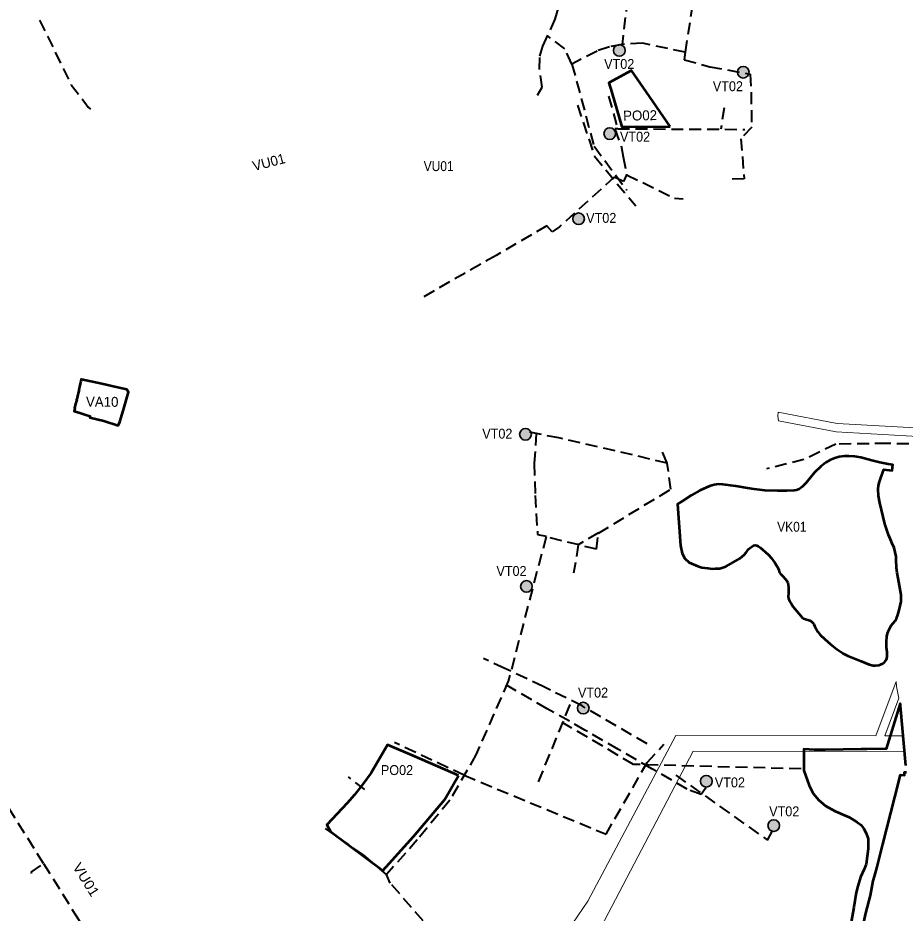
# Model space of a CAD drawing. Extents: x -650145 to -642675, y -1074338 to -1066724.
# Drawn here: x -646953 to -645166, y -1071699 to -1069896 of the extents above; entities that cross this region are included whole.
import ezdxf

# ---------------------------------------------------------------- set-up
doc = ezdxf.new("R2010")
doc.units = 0
doc.header["$LTSCALE"] = 8
doc.linetypes.add('MEDIUM_DASHED', pattern=[4.5, 3, -1.5])
for name, color, linetype in [('1', 7, 'Continuous'), ('17', 7, 'Continuous'), ('2', 7, 'Continuous'), ('3', 7, 'Continuous'), ('5', 7, 'Continuous')]:
    doc.layers.add(name, color=color, linetype=linetype)
for name, color, linetype, lineweight in [('12', 7, 'MEDIUM_DASHED', 40), ('15', 7, 'Continuous', 13), ('45', 7, 'Continuous', 53), ('46', 7, 'Continuous', 53), ('60', 7, 'Continuous', 53)]:
    doc.layers.add(name, color=color, linetype=linetype, lineweight=lineweight)

msp = doc.modelspace()

# ---------------------------------------------------------------- hatches: boundary and pattern name
at = {"layer": '15'}
for points in [[(-645729.982, -1069961.372, 1), (-645753.507, -1069961.372, 1)], [(-645480.488, -1070005.174, 1), (-645504.013, -1070005.174, 1)], [(-645749.33, -1070128.96, 1), (-645772.855, -1070128.96, 1)], [(-645812.096, -1070300.527, 1), (-645835.621, -1070300.527, 1)], [(-645919.09, -1070734.667, 1), (-645942.615, -1070734.667, 1)], [(-645917.104, -1071041.111, 1), (-645940.629, -1071041.111, 1)], [(-645802.757, -1071286.29, 1), (-645826.282, -1071286.29, 1)], [(-645554.856, -1071433.585, 1), (-645578.381, -1071433.585, 1)], [(-645418.959, -1071522.908, 1), (-645442.484, -1071522.908, 1)]]:
    msp.add_hatch(color=256, dxfattribs=at).paths.add_polyline_path(points)

# ---------------------------------------------------------------- linework, layer by layer
at = {"layer": '12'}
for p, q in [((-645530.465, -1070076.92), (-645537.502, -1070120.198)), ((-645787.95, -1070966.128), (-645887.342, -1070941.864)), ((-645904.71, -1071434.718), (-645838.309, -1071272.923)), ((-645713.277, -1071399.789), (-645855.82, -1071315.589)), ((-646054.42, -1071421.627), (-646194.458, -1071355.655)), ((-645375.745, -1071408.757), (-645713.277, -1071399.789)), ((-646254.398, -1071450.366), (-646287.777, -1071424.84))]:
    msp.add_line(p, q, dxfattribs=at)
for points in [[(-645612.686, -1069456.467), (-645628.75, -1069545.873), (-645654.668, -1069623.875), (-645674.387, -1069676.46), (-645706.032, -1069763.934), (-645725.616, -1069858.975), (-645736.083, -1069949.319)], [(-645537.006, -1069644.608), (-645531.552, -1069695.67), (-645540.071, -1069746.311), (-645570.504, -1069798.227), (-645587.257, -1069841.96), (-645594.542, -1069870.205), (-645609.199, -1069964.997), (-645695.3, -1069946.789), (-645735.674, -1069949.294), (-645761.611, -1069954.176), (-645786.679, -1069962.538), (-645837.185, -1069988.794), (-645851.6, -1069958.035), (-645886.355, -1069931.852)], [(-645906.816, -1070051.7), (-645897.34, -1070035.615), (-645902.834, -1069999.35), (-645901.735, -1069972.609), (-645895.874, -1069952.462), (-645870.943, -1069898.484), (-645862.678, -1069869.213), (-645849.656, -1069810.695), (-645844.459, -1069786.925), (-645843.101, -1069776.602)], [(-646909.766, -1069900.481), (-646846.095, -1070030.546), (-646811.614, -1070075.327), (-646807.189, -1070079.418)], [(-645609.199, -1069964.997), (-645611.007, -1069980.138), (-645559.306, -1069994.087), (-645478.278, -1070009.272), (-645476.409, -1070045.777), (-645475.095, -1070115.938), (-645496.905, -1070139.324), (-645490.337, -1070219.995), (-645518.762, -1070220.564)], [(-645837.185, -1069988.794), (-645792.73, -1070154.35), (-645726.373, -1070242.826)], [(-645763.769, -1070053.49), (-645745.016, -1070119.16), (-645488.654, -1070120.442)], [(-645826.322, -1070071.476), (-645791.882, -1070174.421), (-645708.828, -1070274.697)], [(-645745.016, -1070119.16), (-645750.773, -1070119.546), (-645737.216, -1070156.772), (-645734.164, -1070175.48), (-645727.06, -1070211.99), (-645630.95, -1070258.73), (-645613.049, -1070260.16)], [(-645727.06, -1070211.99), (-645733.17, -1070225.623), (-645751.944, -1070216.719), (-645862.549, -1070316.813), (-645877.139, -1070326.682), (-645887.867, -1070314.667), (-645989.89, -1070374.31), (-646136.792, -1070457.926)], [(-645645.314, -1070792.546), (-645863.469, -1070742.026), (-645925.077, -1070730.137)], [(-645909.628, -1070733.118), (-645913.153, -1070793.741), (-645911.597, -1070858.189), (-645906.549, -1070936.386), (-645889.059, -1070939.608)], [(-644716.965, -1070734.034), (-644976.129, -1070756.486), (-645086.887, -1070754.876), (-645202.78, -1070753.267), (-645305.795, -1070754.34), (-645369.783, -1070785.657), (-645445.374, -1070804.496)], [(-645638.383, -1070845.262), (-645645.314, -1070792.546), (-645658.84, -1070762.42)], [(-645787.95, -1070966.128), (-645783.846, -1070933.893), (-645638.383, -1070845.262)], [(-645889.511, -1070941.335), (-645965.547, -1071232.088), (-646030.617, -1071380.071), (-646083.181, -1071471.838), (-646148.926, -1071551.731), (-646210.712, -1071621.148), (-646257.454, -1071581.884), (-646334.001, -1071528.434)], [(-645783.721, -1070932.909), (-645824.424, -1070957.108), (-645833.925, -1071014.113)], [(-645685.92, -1071358.056), (-645816.424, -1071281.963), (-645895.068, -1071242.641), (-645972.753, -1071206.196), (-646015.628, -1071186.357)], [(-645568.545, -1071446.977), (-645568.85, -1071448.81), (-645576.682, -1071460.349), (-645605.23, -1071449.68), (-645676.24, -1071408.26), (-645743.83, -1071369.64), (-645811.23, -1071330.74), (-645886.93, -1071287.36), (-645969.116, -1071240.205)], [(-646901.7, -1071599.29), (-646997.62, -1071446.82), (-647011, -1071454.09), (-647015.17, -1071448), (-647045.84, -1071382.28), (-647050.73, -1071380.13), (-647063.41, -1071364.59), (-647084.37, -1071371.2)], [(-646054.42, -1071421.627), (-645768.62, -1071540.17), (-645685.873, -1071396.078), (-645651.868, -1071358.68)], [(-645627.85, -1071421.652), (-645443.026, -1071552.428), (-645433.722, -1071535.133)], [(-646925.38, -1071619.26), (-646926.8, -1071616.72), (-646901.7, -1071599.29)], [(-646901.7, -1071599.29), (-646836.01, -1071704.74), (-646804.94, -1071754.31)], [(-645979.173, -1071891.235), (-646007.318, -1071860.17), (-646113.522, -1071742.176), (-646203.196, -1071638.82), (-646210.712, -1071621.148)]]:
    msp.add_lwpolyline(points, dxfattribs=at)
at = {"layer": '15'}
for points in [[(-645421.999, -1070689.793), (-645422.175, -1070698.418), (-645421.274, -1070707.252)], [(-645103.193, -1070978.912), (-645049.006, -1070727.131), (-645303.017, -1070712.927), (-645421.999, -1070689.793)], [(-645421.274, -1070707.252), (-645305.123, -1070729.835), (-645069.81, -1070742.995)], [(-645985.984, -1071889.912), (-645875.751, -1071778.476), (-645805.025, -1071675.361), (-645627.872, -1071341.184), (-645225.385, -1071341.796), (-645184.278, -1071232.417)], [(-645184.278, -1071232.417), (-645183.56, -1071242.5), (-645178.87, -1071266.352), (-645207.234, -1071341.824), (-645170.274, -1071341.88), (-645167.04, -1071373.884), (-645592.784, -1071373.238), (-645786.781, -1071742.105), (-645804.579, -1071731.285)]]:
    msp.add_lwpolyline(points, dxfattribs=at)
at = {"layer": '15', "lineweight": 35}
for centre in [(-645741.744, -1069961.372), (-645492.25, -1070005.174), (-645761.092, -1070128.96), (-645823.858, -1070300.527), (-645930.852, -1070734.667), (-645928.866, -1071041.111), (-645814.519, -1071286.29), (-645566.618, -1071433.585), (-645430.721, -1071522.908)]:
    msp.add_circle(centre, 11.762, dxfattribs=at)
at = {"layer": '45'}
for points in [[(-645192.548, -1070953.47), (-645193.51, -1070951.2), (-645199.714, -1070937.126), (-645206.872, -1070914.991), (-645216.991, -1070872.38), (-645219.351, -1070858.481), (-645220.312, -1070845.02), (-645219.787, -1070837.502), (-645217.778, -1070830.159), (-645215.063, -1070822.589), (-645208.696, -1070805.535), (-645192.298, -1070807.665), (-645190.59, -1070796.152), (-645200.111, -1070794.621), (-645217.086, -1070791.58), (-645233.003, -1070787.399), (-645255.407, -1070781.443), (-645267.315, -1070779.162), (-645279.349, -1070778.402), (-645288.343, -1070778.909), (-645298.731, -1070780.176), (-645307.923, -1070782.557), (-645317.677, -1070786.866), (-645325.785, -1070791.428), (-645336.046, -1070799.793), (-645348.318, -1070811.675), (-645366.02, -1070832.94), (-645373.241, -1070840.417), (-645379.448, -1070845.106), (-645385.148, -1070847.387), (-645389.329, -1070848.148), (-645404.15, -1070848.781), (-645423.364, -1070848.402), (-645448.7, -1070847.895), (-645470.235, -1070845.487), (-645483.61, -1070843.208), (-645507.299, -1070838.899), (-645533.268, -1070835.731), (-645542.642, -1070835.35), (-645550.832, -1070836.602), (-645560.079, -1070839.137), (-645579.841, -1070848.008), (-645596.689, -1070857.387), (-645615.817, -1070870.187), (-645624.321, -1070875.224), (-645618.798, -1070958.861), (-645615, -1070975), (-645610, -1070985), (-645601.41, -1070992.83), (-645583.707, -1071000.16), (-645575.406, -1071002.782), (-645563.698, -1071004.618), (-645554.524, -1071005.405), (-645548.534, -1071005.316), (-645539.622, -1071004.966), (-645533.156, -1071003.131), (-645527.302, -1071001.033), (-645521.535, -1070997.886), (-645499.204, -1070984.54), (-645494.223, -1070980.781), (-645490.641, -1070977.722), (-645486.534, -1070972.652), (-645481.466, -1070966.271), (-645477.971, -1070963.036), (-645474.301, -1070960.414), (-645471.418, -1070958.578), (-645468.185, -1070957.966), (-645464.865, -1070958.491), (-645462.069, -1070959.89), (-645457.875, -1070962.949), (-645452.982, -1070967.057), (-645448.001, -1070971.341), (-645441.361, -1070977.635), (-645435.443, -1070984.082), (-645428.541, -1070993.348), (-645423.648, -1071000.865), (-645421.21, -1071006.61), (-645419.026, -1071013.254), (-645417.453, -1071016.051), (-645412.735, -1071020.771), (-645407.492, -1071025.841), (-645404.172, -1071029.687), (-645402.194, -1071033.492), (-645401.408, -1071037.251), (-645400.796, -1071044.157), (-645401.233, -1071054.647), (-645401.408, -1071061.465), (-645400.796, -1071065.748), (-645398.979, -1071070.938), (-645395.234, -1071076.602), (-645395.222, -1071076.62), (-645391.902, -1071082.302), (-645380.193, -1071095.851), (-645373.291, -1071103.543), (-645370.698, -1071105.6), (-645367.028, -1071107.348), (-645362.223, -1071108.484), (-645358.326, -1071109.586), (-645358.203, -1071109.621), (-645354.883, -1071111.631)], [(-645354.883, -1071111.631), (-645353.555, -1071112.92), (-645352, -1071114.429), (-645349.99, -1071117.401), (-645347.631, -1071121.771), (-645345.097, -1071126.754), (-645341.689, -1071132.873), (-645336.884, -1071138.467), (-645328.059, -1071147.471), (-645316.308, -1071157.576), (-645303.551, -1071167.541), (-645291.581, -1071175.845), (-645290.83, -1071176.217), (-645281.707, -1071180.74), (-645254.845, -1071191.919), (-645238.506, -1071198.212), (-645230.555, -1071200.135), (-645225.487, -1071200.398), (-645219.283, -1071199.786), (-645215.351, -1071198.562), (-645211.07, -1071196.464), (-645207.575, -1071193.492), (-645205.049, -1071190.531), (-645202.777, -1071186.423), (-645201.903, -1071181.615), (-645202.34, -1071173.66), (-645203.301, -1071164.132), (-645203.738, -1071152.537), (-645202.951, -1071141.698), (-645201.648, -1071136.226), (-645198.678, -1071128.971), (-645193.872, -1071120.142), (-645186.284, -1071110.216), (-645183.401, -1071105.408), (-645180.692, -1071098.24), (-645177.809, -1071088.625), (-645174.225, -1071071.8), (-645173.788, -1071067.691), (-645174.225, -1071057.989), (-645180.164, -1071024.56), (-645182.261, -1071013.633), (-645183.746, -1071003.786), (-645183.833, -1070986.74), (-645184.357, -1070981.146), (-645185.843, -1070972.23), (-645188.377, -1070963.313), (-645192.548, -1070953.47)], [(-645164.76, -1071401.79), (-645175.4, -1071281.93), (-645175.67, -1071279.45), (-645176.14, -1071277.26), (-645204.341, -1071368.19), (-645243.3, -1071369.02), (-645254.27, -1071369.05), (-645327.08, -1071370.05), (-645348.55, -1071370.559), (-645370.24, -1071368.628), (-645370.24, -1071371.074), (-645370.393, -1071396.574), (-645370.24, -1071411.83), (-645359.64, -1071442), (-645351.06, -1071458.3), (-645340.16, -1071471.63), (-645326.29, -1071483.41), (-645306.77, -1071494.16), (-645286.62, -1071502.67), (-645278.52, -1071506.12), (-645262.36, -1071515.72), (-645255.51, -1071521.55), (-645249.88, -1071528.19), (-645244.4, -1071538.48), (-645240.82, -1071549.6), (-645240.26, -1071569.52), (-645244.81, -1071600.61), (-645248.786, -1071610.383), (-645255.662, -1071626.67), (-645261.094, -1071645.025), (-645264.841, -1071657.687), (-645269.077, -1071687.396), (-645274.868, -1071717.176)], [(-645285.617, -1071875.733), (-645244.798, -1071696.585), (-645235.793, -1071663.703), (-645230.436, -1071634.261), (-645227.905, -1071625.277), (-645222.48, -1071606.08), (-645211.27, -1071560.01), (-645186.67, -1071465.55), (-645175.06, -1071420.93), (-645167.58, -1071421.19), (-645167.37, -1071415.2), (-645163.56, -1071415.3)]]:
    msp.add_lwpolyline(points, dxfattribs=at)
at = {"layer": '46'}
for points in [[(-645639.638, -1070114.895), (-645687.31, -1070045.724), (-645717.36, -1070002.12), (-645762.868, -1070026.606), (-645757.215, -1070045.97), (-645737.075, -1070114.955)], [(-646066.165, -1071422.155), (-646153.5, -1071383.85), (-646208.577, -1071360.044), (-646241.68, -1071416.887), (-646258.487, -1071439.265), (-646275.615, -1071460.886), (-646289.976, -1071477.514), (-646330.914, -1071521.11), (-646324, -1071535), (-646217.978, -1071613.552), (-646211.407, -1071606.247), (-646156.471, -1071545.166), (-646094.063, -1071471.007)]]:
    msp.add_lwpolyline(points, close=True, dxfattribs=at)
at = {"layer": '60'}
msp.add_lwpolyline([(-646825.54, -1070624.03), (-646826.12, -1070623.9), (-646826.45, -1070627.3), (-646827.98, -1070632.83), (-646828.22, -1070632.77), (-646829.55, -1070638.78), (-646829.55, -1070638.78), (-646829.3, -1070638.83), (-646830.51, -1070644.3), (-646830.26, -1070644.35), (-646832.46, -1070654.31), (-646832.7, -1070654.26), (-646834.27, -1070661.39), (-646834.27, -1070661.39), (-646834.4, -1070661.35), (-646835.23, -1070665.08), (-646835.1, -1070665.12), (-646836.6, -1070671.54), (-646836.6, -1070671.54), (-646836.87, -1070671.46), (-646839.27, -1070681.62), (-646838.96, -1070681.72), (-646840.36, -1070687.86), (-646828.7, -1070691.73), (-646816.84, -1070695.43), (-646808.09, -1070698.19), (-646808.76, -1070701.11), (-646780.44, -1070707.59), (-646751.23, -1070717), (-646748.04, -1070709.23), (-646741.52, -1070687.22), (-646730.66, -1070650.07), (-646734.18, -1070644.6), (-646755.21, -1070639.87), (-646755.84, -1070639.88), (-646784.62, -1070633.19)], close=True, dxfattribs=at)

# ---------------------------------------------------------------- texts
at = {"layer": '1', "width": 0.9}
msp.add_text('VK01', height=20, dxfattribs=at).set_placement((-645423.759, -1070930.954))
at = {"layer": '17', "width": 0.95}
for p in [(-645772.41, -1069998.573), (-645553.491, -1070043.441), (-645740.516, -1070145.097), (-645808.603, -1070308.709), (-646017.95, -1070743.342), (-645989.445, -1071019.949), (-645825.148, -1071264.946), (-645549.442, -1071445.886), (-645439.959, -1071504.162)]:
    msp.add_text('VT02', height=20, dxfattribs=at).set_placement(p)
at = {"layer": '2'}
msp.add_text('VU01', height=20, rotation=14.511, dxfattribs=at).set_placement((-646477.81, -1070204.543))
at = {"layer": '2', "width": 0.9}
msp.add_text('VU01', height=20, dxfattribs=at).set_placement((-646135.912, -1070204.401))
at = {"layer": '2', "width": 1.1}
msp.add_text('VU01', height=20, rotation=302.088, dxfattribs=at).set_placement((-646844.301, -1071605.934))
at = {"layer": '3'}
msp.add_text('VA10', height=20, rotation=359.629, dxfattribs=at).set_placement((-646816.427, -1070678.964))
at = {"layer": '5'}
msp.add_text('PO02', height=20, rotation=1.088, dxfattribs=at).set_placement((-645734, -1070102.958))
at = {"layer": '5', "width": 0.95}
msp.add_text('PO02', height=20, dxfattribs=at).set_placement((-646222.248, -1071421.051))

doc.saveas('drawing.dxf')
